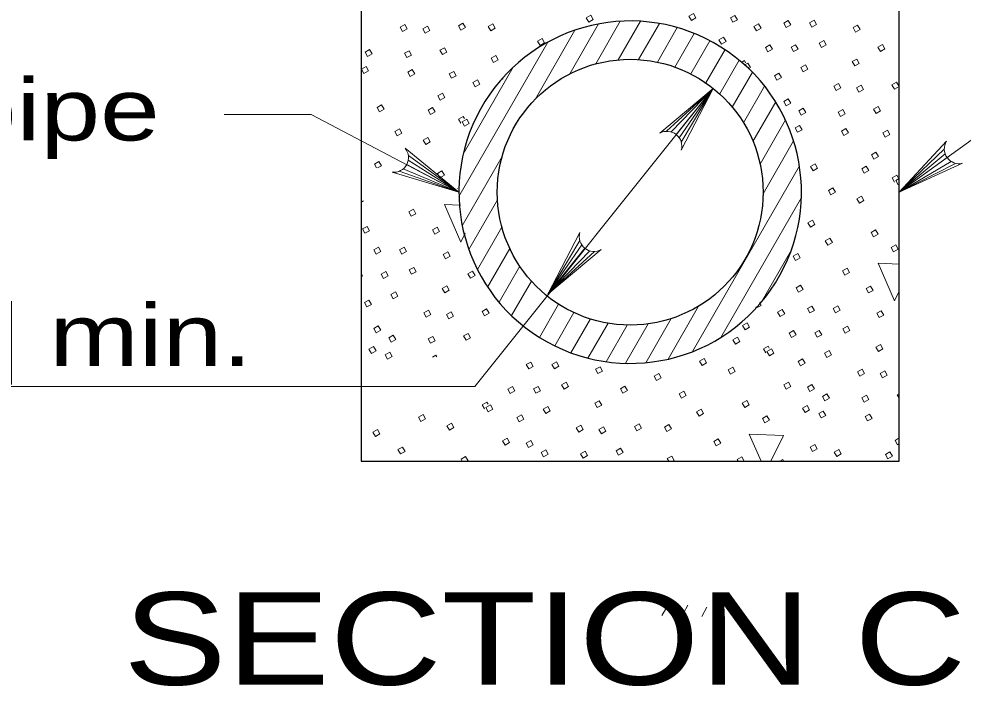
# Model space of a CAD drawing. Extents: x 750.7 to 784.7, y 860.1 to 882.1.
# Drawn here: x 768.322 to 770.769, y 867.661 to 869.391 of the extents above; entities that cross this region are included whole.
import ezdxf
from ezdxf.enums import TextEntityAlignment as Align

# ---------------------------------------------------------------- set-up
doc = ezdxf.new("R2010")
doc.units = 0
doc.header["$LTSCALE"] = 0.064
doc.layers.add('1', color=7, linetype='Continuous', lineweight=13)

msp = doc.modelspace()

# ---------------------------------------------------------------- linework, layer by layer
at = {"layer": '1', "lineweight": 25}
for p, q in [((769.20892, 869.63858), (769.20892, 868.24408)), ((770.60342, 868.24408), (770.60342, 869.641)), ((769.20892, 868.91958), (769.20892, 868.50433)), ((769.20892, 868.39292), (769.20892, 868.24408)), ((769.20892, 868.24408), (770.60342, 868.24408))]:
    msp.add_line(p, q, dxfattribs=at)
at = {"layer": '1'}
for p, q in [((769.65942, 869.18175), (769.76267, 869.36133)), ((769.75, 869.24842), (769.82425, 869.37758)), ((769.81708, 869.27408), (769.8805, 869.38442)), ((769.87525, 869.28442), (769.93275, 869.38442)), ((769.928, 869.28517), (769.98175, 869.37867)), ((769.9765, 869.27858), (770.028, 869.36817)), ((770.0215, 869.26592), (770.07167, 869.35317)), ((769.46242, 868.93), (769.69258, 869.33042)), ((770.06342, 869.24783), (770.11292, 869.33408)), ((770.10225, 869.22458), (770.15192, 869.31092)), ((769.47342, 869.04008), (769.603, 869.2655)), ((770.13817, 869.196), (770.18858, 869.28375)), ((770.17083, 869.16183), (770.22283, 869.25233)), ((769.57533, 869.23483), (769.57667, 869.23558)), ((769.57567, 869.23425), (769.57533, 869.23483)), ((770.19983, 869.12142), (770.2545, 869.21642)), ((769.50358, 868.4375), (770.12117, 869.2105)), ((770.00058, 869.09925), (770.12117, 869.2105)), ((770.0125, 869.0975), (770.12117, 869.2105)), ((770.0255, 869.09075), (770.12117, 869.2105)), ((770.03333, 869.08242), (770.12117, 869.2105)), ((770.03867, 869.07125), (770.12117, 869.2105)), ((769.52758, 869.1715), (769.52767, 869.17158)), ((769.52767, 869.1715), (769.52758, 869.1715)), ((770.22442, 869.07317), (770.28325, 869.1755)), ((769.46758, 869.12008), (769.46142, 869.13092)), ((770.24283, 869.01425), (770.30858, 869.12858)), ((770.25058, 868.93683), (770.32958, 869.07425)), ((770.72017, 869.05333), (770.60342, 868.94133)), ((769.33083, 869.024), (769.46225, 868.94133)), ((769.33117, 869.03633), (769.46225, 868.94133)), ((769.47092, 868.85392), (769.57417, 869.0335)), ((770.72233, 869.04117), (770.60342, 868.94133)), ((770.72758, 869.031), (770.60342, 868.94133)), ((770.73833, 869.021), (770.60342, 868.94133)), ((769.24858, 869.00458), (769.243, 869.01442)), ((769.30742, 868.9955), (769.46225, 868.94133)), ((769.31767, 869.00183), (769.46225, 868.94133)), ((769.32692, 869.01325), (769.46225, 868.94133)), ((770.06792, 868.528), (770.34475, 869.00958)), ((770.74942, 869.01617), (770.60342, 868.94133)), ((770.59142, 868.96758), (770.58533, 868.97842)), ((770.59442, 868.97158), (770.60342, 868.97667)), ((769.4585, 868.95042), (769.45875, 868.9505)), ((769.45883, 868.94992), (769.4585, 868.95042)), ((769.48792, 868.7925), (769.56217, 868.92167)), ((770.14142, 868.56492), (770.34975, 868.92742)), ((769.46608, 868.90792), (769.42475, 868.90958)), ((769.51033, 868.7405), (769.57367, 868.85075)), ((769.77558, 868.81575), (769.69275, 868.67667)), ((769.78083, 868.8045), (769.69275, 868.67667)), ((769.53667, 868.69533), (769.59408, 868.79525)), ((769.78867, 868.79617), (769.69275, 868.67667)), ((769.80167, 868.78933), (769.69275, 868.67667)), ((769.81358, 868.78767), (769.69275, 868.67667)), ((770.24583, 868.65558), (770.324, 868.79158)), ((769.56625, 868.65583), (769.62, 868.74942)), ((770.60342, 868.75483), (770.54867, 868.75708)), ((769.59858, 868.62125), (769.65008, 868.71075)), ((769.67083, 868.56492), (769.72042, 868.65117)), ((769.71042, 868.54292), (769.76008, 868.62925)), ((770.00433, 868.5085), (770.08333, 868.64583)), ((769.75242, 868.52492), (769.80283, 868.61267)), ((769.94683, 868.49933), (770.0125, 868.61367)), ((769.79675, 868.51117), (769.84875, 868.60158)), ((769.84375, 868.50183), (769.89833, 868.59683)), ((769.89358, 868.49767), (769.95233, 868.59992)), ((770.25767, 868.52467), (770.25158, 868.5355)), ((769.50358, 868.4375), (767.01692, 868.4375)), ((770.59833, 868.41617), (770.60342, 868.419)), ((770.60342, 868.40717), (770.59833, 868.41617)), ((769.52883, 868.3795), (769.52275, 868.39033)), ((770.21492, 868.31425), (770.2455, 868.24408)), ((770.59267, 868.298), (770.60342, 868.30408)), ((769.47067, 868.24408), (769.46783, 868.24908)), ((770.00592, 868.24408), (770.00225, 868.25067)), ((770.18617, 868.24408), (770.18367, 868.24842)), ((770.044, 867.84975), (770.05583, 867.87033)), ((769.9885, 867.84408), (769.99983, 867.86383)), ((770.09158, 867.84158), (770.10517, 867.86508))]:
    msp.add_line(p, q, dxfattribs=at)
for points in [[(769.79225, 869.39333), (769.80408, 869.4), (769.8105, 869.38883), (769.79858, 869.38208)], [(770.05842, 869.39775), (770.07025, 869.40442), (770.07658, 869.39317), (770.06475, 869.3865)], [(770.16575, 869.39308), (770.17758, 869.39983), (770.18392, 869.38858), (770.17208, 869.38183)], [(770.30408, 869.38), (770.31592, 869.38675), (770.32225, 869.3755), (770.31042, 869.36875)], [(770.37083, 869.38033), (770.38267, 869.38708), (770.389, 869.37583), (770.37717, 869.36908)], [(769.31008, 869.36917), (769.32192, 869.37583), (769.32833, 869.36458), (769.31642, 869.35792)], [(769.36883, 869.36475), (769.38067, 869.37142), (769.38708, 869.36017), (769.37517, 869.3535)], [(769.46083, 869.3725), (769.47267, 869.37925), (769.479, 869.368), (769.46717, 869.36125)], [(769.53842, 869.37083), (769.55025, 869.37758), (769.55658, 869.36633), (769.54475, 869.35958)], [(770.227, 869.37083), (770.23883, 869.37758), (770.24517, 869.36633), (770.23333, 869.35958)], [(770.48383, 869.36792), (770.49567, 869.37467), (770.502, 869.36342), (770.49017, 869.35667)], [(769.66617, 869.33308), (769.678, 869.33983), (769.68433, 869.32858), (769.6725, 869.32183)], [(770.13625, 869.33633), (770.14808, 869.343), (770.1545, 869.33175), (770.14258, 869.32508)], [(769.41308, 869.30925), (769.425, 869.316), (769.43133, 869.30475), (769.4195, 869.298)], [(770.25642, 869.31675), (770.26825, 869.32342), (770.27458, 869.31217), (770.26275, 869.3055)], [(770.32308, 869.31708), (770.335, 869.32375), (770.34133, 869.3125), (770.3295, 869.30583)], [(770.39592, 869.32775), (770.40775, 869.33442), (770.41417, 869.32317), (770.40225, 869.3165)], [(770.54825, 869.31758), (770.56008, 869.32433), (770.56642, 869.31308), (770.55458, 869.30633)], [(769.219, 869.30475), (769.23083, 869.3115), (769.23725, 869.30025), (769.22533, 869.2935)], [(769.32117, 869.30142), (769.333, 869.30817), (769.33933, 869.29692), (769.3275, 869.29017)], [(769.54583, 869.28892), (769.55775, 869.29567), (769.56408, 869.28442), (769.55217, 869.27767)], [(769.20958, 869.26042), (769.22142, 869.26717), (769.22775, 869.25592), (769.21592, 869.24917)], [(770.34825, 869.26442), (770.36008, 869.27117), (770.36642, 869.25992), (770.35458, 869.25317)], [(770.48167, 869.27992), (770.4935, 869.28667), (770.49983, 869.27542), (770.488, 869.26867)], [(769.32958, 869.2525), (769.34142, 869.25925), (769.34775, 869.248), (769.33592, 869.24125)], [(769.43692, 869.24792), (769.44875, 869.25467), (769.45508, 869.24342), (769.44325, 869.23667)], [(770.27992, 869.24325), (770.29175, 869.24992), (770.29808, 869.23867), (770.28625, 869.232)], [(769.49817, 869.22567), (769.51, 869.23233), (769.51633, 869.22117), (769.5045, 869.21442)], [(770.434, 869.21658), (770.44583, 869.22333), (770.45217, 869.21208), (770.44033, 869.20542)], [(770.49275, 869.21225), (770.50458, 869.21892), (770.51092, 869.20767), (770.49908, 869.201)], [(770.58467, 869.22), (770.5965, 869.22675), (770.60283, 869.2155), (770.591, 869.20875)], [(769.4075, 869.19108), (769.41933, 869.19783), (769.42567, 869.18658), (769.41383, 869.17992)], [(769.24992, 869.16092), (769.26175, 869.16758), (769.26808, 869.15633), (769.25625, 869.14967)], [(770.30392, 869.17625), (770.31575, 869.183), (770.32208, 869.17175), (770.31025, 869.165)], [(769.38233, 869.15425), (769.39417, 869.161), (769.4005, 869.14975), (769.38867, 869.143)], [(770.34292, 869.15225), (770.35475, 869.15892), (770.36108, 869.14775), (770.34925, 869.141)], [(770.445, 869.14892), (770.45692, 869.15567), (770.46325, 869.14442), (770.45133, 869.13767)], [(770.537, 869.15675), (770.54883, 869.16342), (770.55517, 869.15225), (770.54333, 869.1455)], [(769.47058, 869.12408), (769.48242, 869.13083), (769.48875, 869.11958), (769.47692, 869.11283)], [(769.296, 869.09858), (769.30783, 869.10533), (769.31417, 869.09408), (769.30233, 869.08733)], [(770.3335, 869.10792), (770.34533, 869.11458), (770.35167, 869.10333), (770.33983, 869.09667)], [(770.45342, 869.1), (770.46533, 869.10675), (770.47167, 869.0955), (770.45983, 869.08875)], [(770.56075, 869.09542), (770.57267, 869.10217), (770.579, 869.09092), (770.56708, 869.08417)], [(769.36992, 869.07658), (769.38175, 869.08333), (769.38808, 869.07208), (769.37625, 869.06533)], [(770.53133, 869.03858), (770.54317, 869.04533), (770.5495, 869.03408), (770.53767, 869.02733)], [(769.4065, 868.98967), (769.41833, 868.99633), (769.42467, 868.98508), (769.41283, 868.97842)], [(770.37375, 869.00833), (770.38558, 869.01508), (770.39192, 869.00383), (770.38008, 868.99708)], [(770.50617, 869.00175), (770.518, 869.0085), (770.52433, 868.99725), (770.5125, 868.9905)], [(770.41983, 868.94608), (770.43175, 868.95275), (770.43808, 868.9415), (770.42617, 868.93483)], [(770.49375, 868.92408), (770.50558, 868.93083), (770.51192, 868.91958), (770.50008, 868.91283)], [(769.33242, 868.89025), (769.34425, 868.89692), (769.35058, 868.88567), (769.33875, 868.879)], [(769.21208, 868.84608), (769.224, 868.85275), (769.23033, 868.8415), (769.2185, 868.83483)], [(769.39358, 868.84383), (769.40542, 868.85058), (769.41175, 868.83933), (769.39992, 868.83258)], [(770.36692, 868.86192), (770.37875, 868.86867), (770.38508, 868.85742), (770.37325, 868.85067)], [(770.53033, 868.83717), (770.54225, 868.84383), (770.54858, 868.83258), (770.53667, 868.82592)], [(769.24158, 868.79192), (769.25342, 868.79867), (769.25975, 868.78742), (769.24792, 868.78067)], [(769.30825, 868.79225), (769.32008, 868.799), (769.32642, 868.78775), (769.31458, 868.781)], [(770.41183, 868.815), (770.42375, 868.82175), (770.43008, 868.8105), (770.41817, 868.80375)], [(770.58242, 868.79792), (770.59425, 868.80467), (770.60058, 868.79342), (770.58875, 868.78667)], [(769.42125, 868.77983), (769.43308, 868.78658), (769.4395, 868.77533), (769.42758, 868.76858)], [(770.3285, 868.77542), (770.34042, 868.78217), (770.34675, 868.77092), (770.33483, 868.76417)], [(769.26058, 868.729), (769.27242, 868.73575), (769.27875, 868.7245), (769.26692, 868.71775)], [(769.33342, 868.73967), (769.34525, 868.74633), (769.35158, 868.73508), (769.33975, 868.72842)], [(769.48567, 868.7295), (769.49758, 868.73625), (769.50392, 868.725), (769.49208, 868.71825)], [(770.45625, 868.73767), (770.46808, 868.74442), (770.4745, 868.73317), (770.46258, 868.72642)], [(769.28567, 868.67633), (769.29758, 868.68308), (769.30392, 868.67183), (769.29208, 868.66508)], [(769.41908, 868.69183), (769.431, 868.69858), (769.43733, 868.68733), (769.4255, 868.68058)], [(770.336, 868.6935), (770.34783, 868.70025), (770.35417, 868.689), (770.34233, 868.68225)], [(770.51742, 868.69133), (770.52925, 868.698), (770.53558, 868.68683), (770.52375, 868.68008)], [(769.21733, 868.65517), (769.22917, 868.66183), (769.2355, 868.65058), (769.22367, 868.64392)], [(769.37142, 868.62858), (769.38325, 868.63525), (769.38958, 868.624), (769.37775, 868.61733)], [(769.43017, 868.62417), (769.442, 868.63083), (769.44833, 868.61958), (769.4365, 868.61292)], [(769.52217, 868.63192), (769.534, 868.63867), (769.54033, 868.62742), (769.5285, 868.62067)], [(770.28833, 868.63025), (770.30017, 868.637), (770.3065, 868.62575), (770.29467, 868.619)], [(770.36542, 868.63942), (770.37725, 868.64617), (770.38358, 868.63492), (770.37175, 868.62817)], [(770.43217, 868.63975), (770.444, 868.6465), (770.45033, 868.63525), (770.4385, 868.6285)], [(770.54517, 868.62733), (770.557, 868.63408), (770.56333, 868.62283), (770.5515, 868.61608)], [(769.24142, 868.58817), (769.25325, 868.59492), (769.25958, 868.58367), (769.24775, 868.57692)], [(770.19758, 868.59575), (770.20942, 868.60242), (770.21575, 868.59117), (770.20392, 868.5845)], [(770.31775, 868.57617), (770.32958, 868.58283), (770.33592, 868.57158), (770.32408, 868.56492)], [(770.38442, 868.5765), (770.39633, 868.58317), (770.40267, 868.57192), (770.39075, 868.56525)], [(770.45725, 868.58717), (770.46908, 868.59383), (770.47542, 868.58258), (770.46358, 868.57592)], [(769.28033, 868.56417), (769.29217, 868.57092), (769.2985, 868.55967), (769.28667, 868.55292)], [(769.3825, 868.56083), (769.39433, 868.56758), (769.40067, 868.55633), (769.38883, 868.54958)], [(769.47442, 868.56867), (769.48633, 868.57542), (769.49267, 868.56417), (769.48075, 868.55742)], [(770.17242, 868.55883), (770.18425, 868.56558), (770.19058, 868.55433), (770.17875, 868.54758)], [(769.22917, 868.53433), (769.24108, 868.54108), (769.24742, 868.52983), (769.2355, 868.52308)], [(770.26067, 868.52867), (770.2725, 868.53542), (770.27883, 868.52417), (770.267, 868.51742)], [(770.40958, 868.52383), (770.42142, 868.53058), (770.42775, 868.51933), (770.41592, 868.51258)], [(770.543, 868.53933), (770.55483, 868.54608), (770.56117, 868.53483), (770.54933, 868.52808)], [(769.27092, 868.51983), (769.28275, 868.5265), (769.28908, 868.51533), (769.27725, 868.50858)], [(770.08617, 868.50317), (770.098, 868.50992), (770.10433, 868.49867), (770.0925, 868.49192)], [(770.34125, 868.50267), (770.35308, 868.50933), (770.35942, 868.49808), (770.34758, 868.49142)], [(769.63658, 868.49425), (769.6485, 868.501), (769.65483, 868.48975), (769.643, 868.483)], [(769.70333, 868.49458), (769.71517, 868.50133), (769.7215, 868.49008), (769.70967, 868.48333)], [(769.81633, 868.48217), (769.82817, 868.48883), (769.8345, 868.47758), (769.82267, 868.47092)], [(770.16, 868.48117), (770.17183, 868.48792), (770.17817, 868.47667), (770.16633, 868.46992)], [(770.49533, 868.476), (770.50717, 868.48275), (770.5135, 868.4715), (770.50167, 868.46475)], [(769.96817, 868.46433), (769.98, 868.47108), (769.98633, 868.45983), (769.9745, 868.45308)], [(770.55408, 868.47158), (770.56592, 868.47833), (770.57225, 868.46708), (770.56042, 868.46042)], [(769.58892, 868.43092), (769.60075, 868.43767), (769.60708, 868.42642), (769.59525, 868.41967)], [(769.65567, 868.43125), (769.6675, 868.438), (769.67383, 868.42675), (769.662, 868.42008)], [(769.72842, 868.44192), (769.74033, 868.44867), (769.74667, 868.43742), (769.73483, 868.43067)], [(769.88075, 868.43183), (769.89258, 868.4385), (769.89892, 868.42733), (769.88708, 868.42058)], [(770.30425, 868.44183), (770.31608, 868.4485), (770.32242, 868.43725), (770.31058, 868.43058)], [(770.36525, 868.43567), (770.37708, 868.44242), (770.38342, 868.43117), (770.37158, 868.42442)], [(770.03317, 868.419), (770.045, 868.42575), (770.05133, 868.4145), (770.0395, 868.40775)], [(770.40425, 868.41167), (770.41608, 868.41833), (770.42242, 868.40708), (770.41058, 868.40042)], [(770.50633, 868.40833), (770.51817, 868.41508), (770.52458, 868.40383), (770.51267, 868.39708)], [(769.53192, 868.3835), (769.54375, 868.39017), (769.55008, 868.379), (769.53825, 868.37225)], [(769.68075, 868.37867), (769.69258, 868.38542), (769.69892, 868.37417), (769.68708, 868.36742)], [(769.81417, 868.39417), (769.826, 868.40083), (769.83233, 868.38958), (769.8205, 868.38292)], [(770.19658, 868.39425), (770.2085, 868.401), (770.21483, 868.38975), (770.203, 868.383)], [(770.35308, 868.38183), (770.36492, 868.38858), (770.37125, 868.37733), (770.35942, 868.37058)], [(769.35733, 868.358), (769.36917, 868.36475), (769.3755, 868.3535), (769.36367, 868.34675)], [(769.61242, 868.35742), (769.62425, 868.36417), (769.63058, 868.35292), (769.61875, 868.34617)], [(770.07808, 868.37208), (770.09, 868.37883), (770.09633, 868.36758), (770.0845, 868.36083)], [(770.24867, 868.355), (770.2605, 868.36175), (770.26683, 868.3505), (770.255, 868.34375)], [(770.39475, 868.36733), (770.40667, 868.374), (770.413, 868.36275), (770.40117, 868.35608)], [(770.51475, 868.35942), (770.52658, 868.36617), (770.533, 868.35492), (770.52108, 868.34817)], [(769.43125, 868.336), (769.44308, 868.34275), (769.44942, 868.3315), (769.43758, 868.32475)], [(769.7665, 868.33083), (769.77833, 868.33758), (769.78467, 868.32633), (769.77283, 868.31958)], [(769.91717, 868.33425), (769.92908, 868.341), (769.93542, 868.32975), (769.9235, 868.323)], [(769.99475, 868.3325), (770.00667, 868.33925), (770.013, 868.328), (770.00117, 868.32133)], [(769.23942, 868.31917), (769.25125, 868.32592), (769.25758, 868.31467), (769.24575, 868.30792)], [(769.82525, 868.32642), (769.83708, 868.33317), (769.84342, 868.32192), (769.83158, 868.31517)], [(769.57542, 868.29658), (769.58725, 868.30333), (769.59367, 868.29208), (769.58175, 868.28533)], [(769.63642, 868.2905), (769.64833, 868.29725), (769.65467, 868.286), (769.64275, 868.27925)], [(770.1225, 868.29483), (770.13442, 868.3015), (770.14075, 868.29025), (770.12892, 868.28358)], [(770.37258, 868.28025), (770.38442, 868.28692), (770.39075, 868.27567), (770.37892, 868.269)], [(769.30433, 868.27383), (769.31617, 868.28058), (769.3225, 868.26933), (769.31067, 868.26258)], [(769.67542, 868.26642), (769.68725, 868.27317), (769.69358, 868.26192), (769.68175, 868.25525)], [(769.77758, 868.26317), (769.78942, 868.26983), (769.79575, 868.25858), (769.78392, 868.25192)], [(769.8695, 868.271), (769.88133, 868.27767), (769.88767, 868.26642), (769.87583, 868.25975)], [(770.43508, 868.26775), (770.44692, 868.2745), (770.45325, 868.26325), (770.44142, 868.2565)], [(770.5675, 868.26117), (770.57933, 868.26792), (770.58567, 868.25667), (770.57383, 868.24992)]]:
    msp.add_lwpolyline(points, close=True, dxfattribs=at)
for points in [[(770.19333, 869.27783), (770.20208, 869.28283), (770.20533, 869.27717)], [(770.20142, 869.27042), (770.21117, 869.276), (770.21758, 869.26475), (770.2115, 869.26133)], [(769.983, 869.09425), (770.12117, 869.2105), (770.03833, 869.05)], [(769.46225, 868.94133), (769.07908, 869.1425), (768.85358, 869.1425)], [(770.60342, 868.94133), (770.91325, 869.16508), (771.13117, 869.16508)], [(769.46142, 869.13092), (769.47325, 869.13767), (769.4765, 869.132)], [(770.76767, 869.01625), (770.60342, 868.94133), (770.72617, 869.07367)], [(769.28925, 868.99308), (769.46225, 868.94133), (769.3225, 869.05567)], [(769.243, 869.01442), (769.25492, 869.02117), (769.26125, 869.00992), (769.25125, 869.00425)], [(770.58533, 868.97842), (770.59717, 868.98517), (770.60042, 868.9795)], [(770.60342, 868.96183), (770.60075, 868.96033), (770.59442, 868.97158)], [(769.21458, 868.91875), (769.211, 868.91667), (769.20942, 868.9195)], [(769.42475, 868.90958), (769.46733, 868.81217), (769.47867, 868.83542)], [(769.83117, 868.79258), (769.69275, 868.67667), (769.776, 868.83692)], [(770.54867, 868.75708), (770.59117, 868.65958), (770.60342, 868.68467)], [(769.21008, 868.72758), (769.21208, 868.72417), (769.21008, 868.723)], [(770.24092, 868.65567), (770.24525, 868.648), (770.23342, 868.64125), (770.23175, 868.64425)], [(770.25158, 868.5355), (770.26342, 868.54225), (770.26667, 868.53658)], [(769.39392, 868.51367), (769.40275, 868.51867), (769.405, 868.51467)], [(769.52275, 868.39033), (769.53458, 868.39708), (769.53783, 868.39142)], [(770.27075, 868.24408), (770.30308, 868.3105), (770.21492, 868.31425)], [(770.60342, 868.28925), (770.599, 868.28675), (770.59267, 868.298)], [(769.46783, 868.24908), (769.47967, 868.25575), (769.486, 868.2445), (769.48517, 868.24408)], [(770.00225, 868.25067), (770.01408, 868.25733), (770.02042, 868.24608), (770.01683, 868.24408)], [(770.18367, 868.24842), (770.1955, 868.25517), (770.20175, 868.24408)], [(770.29367, 868.24408), (770.30133, 868.24842), (770.30383, 868.24408)]]:
    msp.add_lwpolyline(points, dxfattribs=at)
at = {"layer": '1', "lineweight": 25}
msp.add_circle((769.90613, 868.94131), 0.34452, dxfattribs=at)
msp.add_arc((769.90613, 868.94132), 0.44387, 238.0369, 237.98785, dxfattribs=at)
at = {"layer": '1'}
for centre, start, end in [((770.00176, 869.06093), 343.46234, 119.28847), ((770.75852, 869.05337), 147.92323, 283.74935), ((769.29326, 869.03112), 264.11023, 39.93636), ((769.8125, 868.82593), 163.3364, 299.16252)]:
    msp.add_arc(centre, 0.03822, start, end, dxfattribs=at)

# ---------------------------------------------------------------- texts
for s, height, width, p in [('Drop pipe', 0.16, 1.3, (767.48092, 869.07542)), ('SECTION C-C', 0.24, 1.25, (768.59242, 867.66417))]:
    msp.add_text(s, height=height, dxfattribs=dict(at, width=width)).set_placement(p)
at = {"layer": '1', "width": 1.3}
msp.add_text('12" [300] min.', height=0.16, dxfattribs=at).set_placement((768.07283, 868.49083), align=Align.CENTER)

doc.saveas('drawing.dxf')
